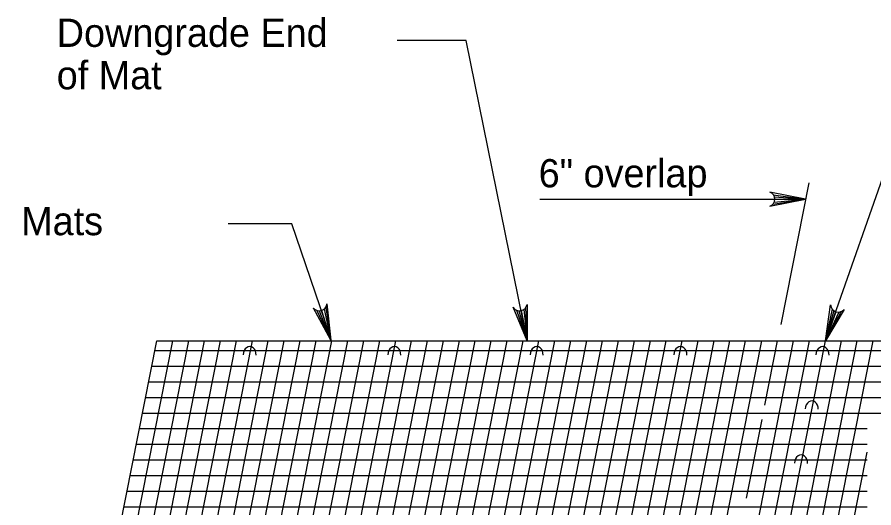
# Model space of a CAD drawing. Extents: x 1083.1 to 1117.1, y 719.4 to 741.4.
# Drawn here: x 1087.509 to 1091.754, y 730.624 to 733.056 of the extents above; entities that cross this region are included whole.
import ezdxf

# ---------------------------------------------------------------- set-up
doc = ezdxf.new("R2010")
doc.units = 0
doc.layers.add('ST_Details', color=7, linetype='Continuous')
doc.layers.add('ST_Text', color=7, linetype='Continuous')

msp = doc.modelspace()

# ---------------------------------------------------------------- linework, layer by layer
at = {"layer": 'ST_Details'}
for p, q in [((1091.5153, 731.4512), (1091.9778, 732.7755)), ((1091.4326, 732.2351), (1091.2938, 731.533)), ((1091.2562, 732.1757), (1091.4164, 732.1533)), ((1090.0998, 732.154), (1091.4164, 732.1533)), ((1091.2543, 732.1286), (1091.4164, 732.1533)), ((1091.2604, 732.139), (1091.4164, 732.1533)), ((1091.2616, 732.1646), (1091.4164, 732.1533)), ((1091.2633, 732.1533), (1091.4164, 732.1533)), ((1089.0386, 731.6173), (1089.0632, 731.4551)), ((1090.0286, 731.6151), (1090.0369, 731.4512)), ((1088.9941, 731.6015), (1089.0632, 731.4551)), ((1089.0063, 731.5996), (1089.0632, 731.4551)), ((1089.0176, 731.6014), (1089.0632, 731.4551)), ((1089.0305, 731.6084), (1089.0632, 731.4551)), ((1089.9828, 731.6037), (1090.0369, 731.4512)), ((1089.9947, 731.6006), (1090.0369, 731.4512)), ((1090.0061, 731.6013), (1090.0369, 731.4512)), ((1090.0197, 731.607), (1090.0369, 731.4512)), ((1091.547, 731.6099), (1091.5153, 731.4512)), ((1091.5557, 731.6011), (1091.5153, 731.4512)), ((1091.5922, 731.5961), (1091.5153, 731.4512)), ((1091.5658, 731.5958), (1091.5153, 731.4512)), ((1091.5803, 731.5938), (1091.5153, 731.4512)), ((1087.6134, 728.076), (1088.2804, 731.4512)), ((1087.6923, 728.076), (1088.3593, 731.4512)), ((1087.7712, 728.076), (1088.4382, 731.4512)), ((1087.85, 728.076), (1088.5171, 731.4512)), ((1087.9289, 728.076), (1088.5959, 731.4512)), ((1087.9507, 730.1819), (1088.2015, 731.4512)), ((1088.0078, 728.076), (1088.6748, 731.4512)), ((1088.0867, 728.076), (1088.7537, 731.4512)), ((1088.1656, 728.076), (1088.8326, 731.4512)), ((1088.2015, 731.4512), (1093.8736, 731.4512)), ((1088.2444, 728.076), (1088.9114, 731.4512)), ((1088.3233, 728.076), (1088.9903, 731.4512)), ((1088.4021, 728.076), (1089.0692, 731.4512)), ((1088.481, 728.076), (1089.1481, 731.4512)), ((1088.5598, 728.076), (1089.227, 731.4512)), ((1088.6388, 728.076), (1089.3058, 731.4512)), ((1088.7176, 728.076), (1089.3848, 731.4512)), ((1088.7965, 728.076), (1089.4636, 731.4512)), ((1088.8754, 728.076), (1089.5425, 731.4512)), ((1088.9543, 728.076), (1089.6213, 731.4512)), ((1089.0332, 728.076), (1089.7003, 731.4512)), ((1089.112, 728.076), (1089.7791, 731.4512)), ((1089.1909, 728.076), (1089.858, 731.4512)), ((1089.2698, 728.076), (1089.9369, 731.4512)), ((1089.556, 729.1251), (1090.0158, 731.4512)), ((1089.645, 729.1765), (1090.0947, 731.4512)), ((1089.7332, 729.2232), (1090.1735, 731.4512)), ((1089.8203, 729.2656), (1090.2524, 731.4512)), ((1089.9069, 729.304), (1090.3313, 731.4512)), ((1089.9926, 729.3387), (1090.4102, 731.4512)), ((1090.0778, 729.37), (1090.489, 731.4512)), ((1090.5547, 731.3842), (1090.5679, 731.4512)), ((1090.5547, 730.9851), (1090.6468, 731.4512)), ((1090.5547, 730.5863), (1090.7256, 731.4512)), ((1090.5547, 730.1872), (1090.8045, 731.4512)), ((1090.5547, 729.7881), (1090.8833, 731.4512)), ((1090.5754, 729.4936), (1090.9623, 731.4512)), ((1090.6564, 729.5047), (1091.0411, 731.4512)), ((1090.7354, 729.5133), (1091.1185, 731.4512)), ((1090.8172, 729.5197), (1091.1988, 731.4512)), ((1090.9761, 729.5254), (1091.3566, 731.4512)), ((1091.0548, 729.5249), (1091.4355, 731.4512)), ((1091.1332, 729.5222), (1091.5144, 731.4512)), ((1091.211, 729.5173), (1091.5933, 731.4512)), ((1091.2145, 731.1321), (1091.2777, 731.4512)), ((1091.2886, 729.5102), (1091.6722, 731.4512)), ((1091.3656, 729.5011), (1091.751, 731.4512)), ((1088.192, 731.4031), (1090.5547, 731.4031)), ((1090.5547, 731.4031), (1093.8641, 731.4031)), ((1091.2551, 731.4031), (1093.8641, 731.4031)), ((1090.1621, 729.3978), (1090.5547, 731.3842)), ((1088.1767, 731.3257), (1090.5547, 731.3257)), ((1090.5547, 731.3257), (1093.8488, 731.3257)), ((1088.1615, 731.2484), (1090.5547, 731.2484)), ((1090.5547, 731.2484), (1093.8336, 731.2484)), ((1088.1462, 731.171), (1090.5547, 731.171)), ((1090.5547, 731.171), (1093.8183, 731.171)), ((1088.1309, 731.0936), (1090.5547, 731.0936)), ((1090.5547, 731.0936), (1093.803, 731.0936)), ((1091.1235, 730.6714), (1091.2006, 731.0619)), ((1088.1156, 731.0162), (1090.5547, 731.0162)), ((1090.2458, 729.4226), (1090.5547, 730.9851)), ((1090.5547, 731.0162), (1091.721, 731.0162)), ((1088.1003, 730.9389), (1090.5547, 730.9389)), ((1090.5547, 730.9389), (1091.721, 730.9389)), ((1091.1629, 728.076), (1091.721, 730.9)), ((1088.085, 730.8615), (1090.5547, 730.8615)), ((1090.5547, 730.8615), (1091.721, 730.8615)), ((1088.0697, 730.7841), (1090.5547, 730.7841)), ((1090.5547, 730.7841), (1091.721, 730.7841)), ((1088.0544, 730.7067), (1090.5547, 730.7067)), ((1090.5547, 730.7067), (1091.721, 730.7067)), ((1088.0391, 730.6294), (1090.5547, 730.6294)), ((1090.5547, 730.6294), (1091.721, 730.6294))]:
    msp.add_line(p, q, dxfattribs=at)
for points in [[(1090.0369, 731.4512), (1089.7341, 732.94), (1089.3923, 732.94)], [(1091.2394, 732.118), (1091.4164, 732.1533), (1091.2394, 732.1887)], [(1089.0566, 731.4845), (1088.87, 732.0311), (1088.5543, 732.0311)], [(1089.0443, 731.6346), (1089.0632, 731.4551), (1088.9768, 731.6136)], [(1090.036, 731.6317), (1090.0369, 731.4512), (1089.9667, 731.6175)], [(1091.6071, 731.6067), (1091.5153, 731.4512), (1091.5403, 731.63)]]:
    msp.add_lwpolyline(points, dxfattribs=at)
for centre, start, end in [((1091.2251, 732.1534), 292.0861, 67.9122), ((1089.0062, 731.6378), 219.4095, 355.2356), ((1089.9984, 731.6386), 213.7063, 349.5325), ((1091.5784, 731.6319), 182.8485, 318.6747)]:
    msp.add_arc(centre, 0.0382, start, end, dxfattribs=at)
for centre in [(1088.6611, 731.3816), (1089.378, 731.3816), (1090.0833, 731.3816), (1090.7956, 731.3816), (1091.4999, 731.3816), (1091.4469, 731.1132), (1091.3938, 730.8449)]:
    msp.add_ellipse(centre, major_axis=(0.0011, 0.041), ratio=0.78812, start_param=4.7124, end_param=7.853993, dxfattribs=at)

# ---------------------------------------------------------------- texts
at = {"layer": 'ST_Text'}
for s, p in [('Downgrade End', (1087.7052, 732.9081)), ('of Mat', (1087.7052, 732.6981)), ('6" overlap', (1090.0934, 732.2121)), ('Erosion Control Mats', (1086.1866, 731.975))]:
    msp.add_text(s, height=0.14, dxfattribs=at).set_placement(p)

doc.saveas('drawing.dxf')
